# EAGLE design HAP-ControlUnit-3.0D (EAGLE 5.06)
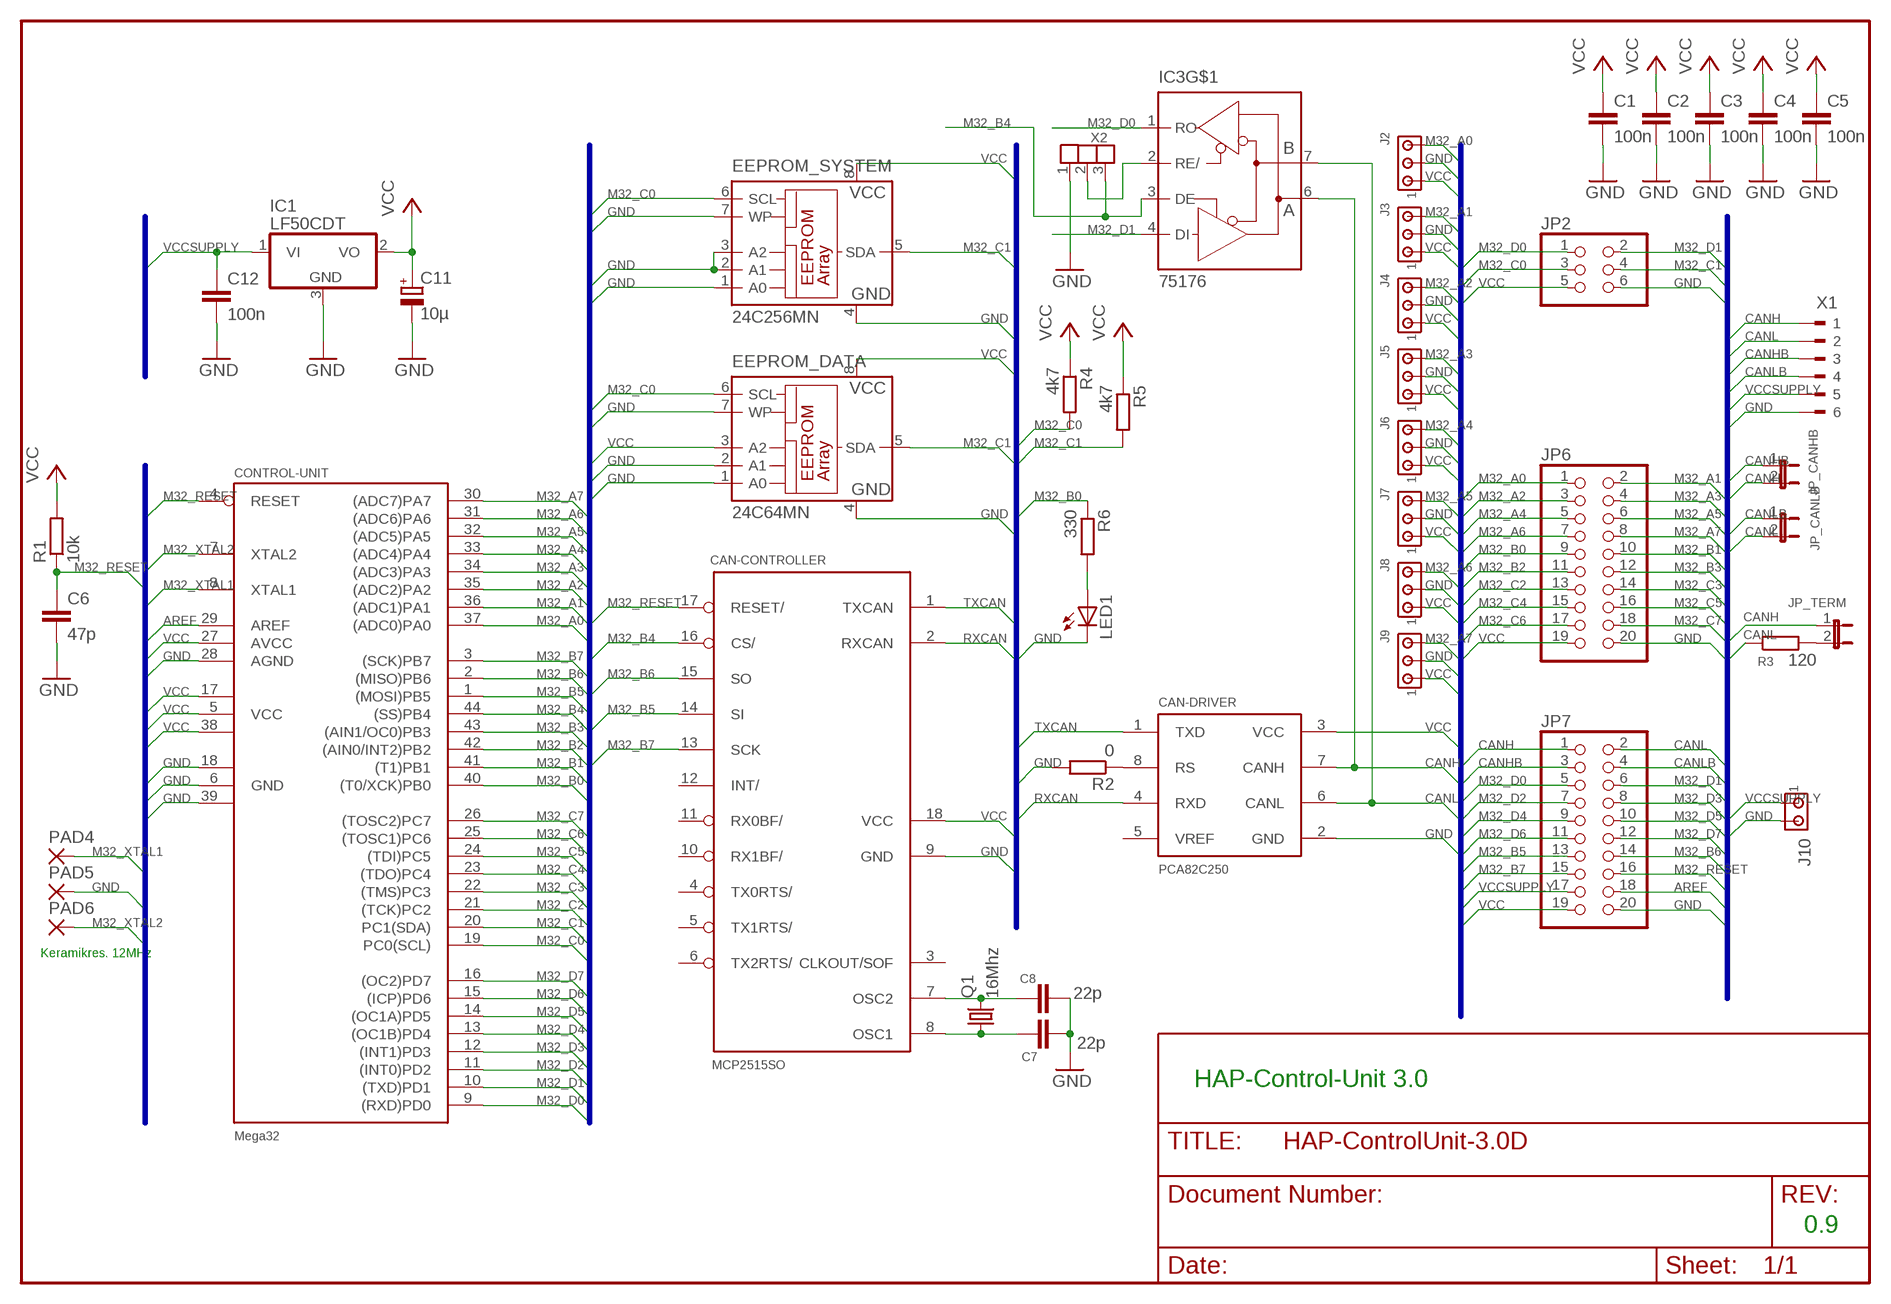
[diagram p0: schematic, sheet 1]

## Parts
C1  100n  C-EUC0805  [C0805]
C2  100n  C-EUC0805  [C0805]
C3  100n  C-EUC0805  [C0805]
C4  100n  C-EUC0805  [C0805]
C5  100n  C-EUC0805  [C0805]
C6  47p  C-EUC0805  [C0805]
C7  22p  C-EUC0805  [C0805]
C8  22p  C-EUC0805  [C0805]
C11  10µ  CPOL-EU153CLV-0405  [153CLV-0405]
C12  100n  C-EUC0805  [C0805]
CAN-CONTROLLER  MCP2515SO  [SO18L]
CAN-DRIVER  PCA82C250  PCA82C251SMD  [SO8]
CONTROL-UNIT  Mega32  MEGA32-A  [TQFP44]
EEPROM_DATA  24C64MN  24C32ASN  [SO-08]
EEPROM_SYSTEM  24C256MN  24C32ASN  [SO-08]
IC1  LF50CDT  7806DT  [TO252]
IC3  75176  [SO8]
J2  MTA03-100  [10X03MTA]
J3  MTA03-100  [10X03MTA]
J4  MTA03-100  [10X03MTA]
J5  MTA03-100  [10X03MTA]
J6  MTA03-100  [10X03MTA]
J7  MTA03-100  [10X03MTA]
J8  MTA03-100  [10X03MTA]
J9  MTA03-100  [10X03MTA]
J10  MTA02-100  [10X02MTA]
JP2  PINHD-2X3  [2X03]
JP6  PINHD-2X10  [2X10]
JP7  PINHD-2X10  [2X10]
JP_CANHB  JP1E  [JP1]
JP_CANLB  JP1E  [JP1]
JP_TERM  JP1E  [JP1]
LED1  LEDCHIP-LED0805  [CHIP-LED0805]
PAD4  1,6/0,9  [1,6/0,9]
PAD5  1,6/0,9  [1,6/0,9]
PAD6  1,6/0,9  [1,6/0,9]
Q1  16Mhz  CRYSTALHC49UP  [HC49UP]
R1  10k  R-EU_R0805  [R0805]
R2  0  R-EU_R0805  [R0805]
R3  120  R-EU_R0805  [R0805]
R4  4k7  R-EU_R0805  [R0805]
R5  4k7  R-EU_R0805  [R0805]
R6  330  R-EU_R0805  [R0805]
X1  180-6  [180-6]
X2  3-P-SMD12ZU  [3-P-SMD1]

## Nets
AREF: CONTROL-UNIT.29(AREF) JP7.18
CANH: CAN-DRIVER.7(CANH) IC3.6(A) JP7.1 JP_CANHB.2 JP_TERM.1 X1.1
CANHB: JP7.3 JP_CANHB.1 X1.3
CANL: CAN-DRIVER.6(CANL) IC3.7(B) JP7.2 JP_CANLB.2 R3.1 X1.2
CANLB: JP7.4 JP_CANLB.1 X1.4
GND [VCC_GND]: C1.2 C2.2 C3.2 C4.2 C5.2 C6.2 C7.2 C8.2 C11.- C12.2 CAN-CONTROLLER.9(GND) CAN-DRIVER.2(GND) CONTROL-UNIT.6(GND) CONTROL-UNIT.18(GND1) CONTROL-UNIT.28(AGND) CONTROL-UNIT.39(GND2) EEPROM_DATA.1(A0) EEPROM_DATA.2(A1) EEPROM_DATA.4(GND) EEPROM_DATA.7(WP) EEPROM_SYSTEM.1(A0) EEPROM_SYSTEM.2(A1) EEPROM_SYSTEM.3(A2) EEPROM_SYSTEM.4(GND) EEPROM_SYSTEM.7(WP) IC1.3(GND) J2.2 J3.2 J4.2 J5.2 J6.2 J7.2 J8.2 J9.2 J10.2 JP2.6 JP6.20 JP7.20 LED1.C PAD5.1(P) R2.2 X1.6 X2.1
M32_A0: CONTROL-UNIT.37((ADC0)PA0) J2.3 JP6.1
M32_A1: CONTROL-UNIT.36((ADC1)PA1) J3.3 JP6.2
M32_A2: CONTROL-UNIT.35((ADC2)PA2) J4.3 JP6.3
M32_A3: CONTROL-UNIT.34((ADC3)PA3) J5.3 JP6.4
M32_A4: CONTROL-UNIT.33((ADC4)PA4) J6.3 JP6.5
M32_A5: CONTROL-UNIT.32((ADC5)PA5) J7.3 JP6.6
M32_A6: CONTROL-UNIT.31((ADC6)PA6) J8.3 JP6.7
M32_A7: CONTROL-UNIT.30((ADC7)PA7) J9.3 JP6.8
M32_B0: CONTROL-UNIT.40((T0/XCK)PB0) JP6.9 R6.1
M32_B1: CONTROL-UNIT.41((T1)PB1) JP6.10
M32_B2: CONTROL-UNIT.42((AIN0/INT2)PB2) JP6.11
M32_B3: CONTROL-UNIT.43((AIN1/OC0)PB3) JP6.12
M32_B4: CAN-CONTROLLER.16(CS/) CONTROL-UNIT.44((SS)PB4) IC3.3(DE) X2.3
M32_B5: CAN-CONTROLLER.14(SI) CONTROL-UNIT.1((MOSI)PB5) JP7.13
M32_B6: CAN-CONTROLLER.15(SO) CONTROL-UNIT.2((MISO)PB6) JP7.14
M32_B7: CAN-CONTROLLER.13(SCK) CONTROL-UNIT.3((SCK)PB7) JP7.15
M32_C0: CONTROL-UNIT.19(PC0(SCL)) EEPROM_DATA.6(SCL) EEPROM_SYSTEM.6(SCL) JP2.3 R4.2
M32_C1: CONTROL-UNIT.20(PC1(SDA)) EEPROM_DATA.5(SDA) EEPROM_SYSTEM.5(SDA) JP2.4 R5.2
M32_C2: CONTROL-UNIT.21((TCK)PC2) JP6.13
M32_C3: CONTROL-UNIT.22((TMS)PC3) JP6.14
M32_C4: CONTROL-UNIT.23((TDO)PC4) JP6.15
M32_C5: CONTROL-UNIT.24((TDI)PC5) JP6.16
M32_C6: CONTROL-UNIT.25((TOSC1)PC6) JP6.17
M32_C7: CONTROL-UNIT.26((TOSC2)PC7) JP6.18
M32_D0: CONTROL-UNIT.9((RXD)PD0) IC3.1(RO) JP2.1 JP7.5
M32_D1: CONTROL-UNIT.10((TXD)PD1) IC3.4(DI) JP2.2 JP7.6
M32_D2: CONTROL-UNIT.11((INT0)PD2) JP7.7
M32_D3: CONTROL-UNIT.12((INT1)PD3) JP7.8
M32_D4: CONTROL-UNIT.13((OC1B)PD4) JP7.9
M32_D5: CONTROL-UNIT.14((OC1A)PD5) JP7.10
M32_D6: CONTROL-UNIT.15((ICP)PD6) JP7.11
M32_D7: CONTROL-UNIT.16((OC2)PD7) JP7.12
M32_RESET: C6.1 CAN-CONTROLLER.17(RESET/) CONTROL-UNIT.4(RESET) JP7.16 R1.1
M32_XTAL1: CONTROL-UNIT.8(XTAL1) PAD4.1(P)
M32_XTAL2: CONTROL-UNIT.7(XTAL2) PAD6.1(P)
N$1: LED1.A R6.2
N$2: IC3.2(RE/) X2.2
N$4: CAN-DRIVER.8(RS) R2.1
N$5: C7.1 CAN-CONTROLLER.8(OSC1) Q1.1
N$6: JP_TERM.2 R3.2
N$7: C8.1 CAN-CONTROLLER.7(OSC2) Q1.2
RXCAN: CAN-CONTROLLER.2(RXCAN) CAN-DRIVER.4(RXD)
TXCAN: CAN-CONTROLLER.1(TXCAN) CAN-DRIVER.1(TXD)
VCC [VCC_GND]: C1.1 C2.1 C3.1 C4.1 C5.1 C11.+ CAN-CONTROLLER.18(VCC) CAN-DRIVER.3(VCC) CONTROL-UNIT.5(VCC) CONTROL-UNIT.17(VCC1) CONTROL-UNIT.27(AVCC) CONTROL-UNIT.38(VCC2) EEPROM_DATA.3(A2) EEPROM_DATA.8(VCC) EEPROM_SYSTEM.8(VCC) IC1.2(VO) J2.1 J3.1 J4.1 J5.1 J6.1 J7.1 J8.1 J9.1 JP2.5 JP6.19 JP7.19 R1.2 R4.1 R5.1
VCCSUPPLY [VCC_GND]: C12.1 IC1.1(VI) J10.1 JP7.17 X1.5
Unconnected: CAN-CONTROLLER.3(CLKOUT/SOF) CAN-CONTROLLER.4(TX0RTS/) CAN-CONTROLLER.5(TX1RTS/) CAN-CONTROLLER.6(TX2RTS/) CAN-CONTROLLER.10(RX1BF/) CAN-CONTROLLER.11(RX0BF/) CAN-CONTROLLER.12(INT/) CAN-DRIVER.5(VREF)

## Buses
M32_RESET,M32_XTAL2,M32_XTAL1,M32_AREF,M32_AVCC,M32_AGND,M32_A[0..7],M32_B[0..7],M32_C[0..7],M32_D[0..7],VCC,GND,TXCAN,RXCAN,CANH,CANHB,CANL,CANLB,VCCSUPPLY,M32_XTAL1,M32_XTAL2,MCP_OSC1,MCP_OSC2,AREF

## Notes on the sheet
- Keramikres. 12MHz
- HAP-Control-Unit 3.0
- 0.9

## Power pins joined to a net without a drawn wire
GND: IC3.5(GND)
VCC: IC3.8(VCC)

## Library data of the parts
C1-C8 C12 = rcl:C-EU: CAPACITOR, European symbol
C11 = rcl:CPOL-EU: POLARIZED CAPACITOR, European symbol
CAN-CONTROLLER = MCP2515_MT:MCP2515*: MCP2515 Standalone CAN-Controller by Microchip Eagle-Lib. by MartinThomas
CAN-DRIVER = 82C250SMD:PCA82C251SMD
CONTROL-UNIT = atmel:MEGA32: MICROCONTROLLER 32 Kbytes FLASH 2 Kbytes SRAM 1 Kbytes EEPROM USART 8-channel 10 bit ADC Source: www.atmel.com .. doc2503.pdf
EEPROM_DATA EEPROM_SYSTEM = microchip:24*: Serial EEPROM I2C
IC1 = linear:78*: Positive VOLTAGE REGULATOR Source: http://cache.national.com/ds/LM/LM78L05.pdf http://www.fairchildsemi.com/ds/LM/LM7805.pdf
IC3 = OWN:75176
J2-J9 = con-amp:MTA03-100: AMP connector
J10 = con-amp:MTA02-100: AMP connector
JP2 = pinhead:PINHD-2X3: PIN HEADER
JP6 JP7 = pinhead:PINHD-2X10: PIN HEADER
JP_CANHB JP_CANLB JP_TERM = jumper:JP1E: JUMPER
LED1 = led:LED: LED
PAD4-PAD6 = wirepad:1,6/0,9: THROUGH-HOLE PAD
Q1 = crystal:CRYSTAL: CRYSTAL
R1-R6 = rcl:R-EU_: RESISTOR, European symbol
X1 = con-weidmueller-sl35:180-6: WEIDMUELLER CLAMP CONNECTOR
X2 = OWN:3-P-SMD

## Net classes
0 default: width 0.15 mm, drill 0.3 mm, clearance 0.15 mm
1 VCC_GND: width 0.25 mm, drill 0.3 mm, clearance 0.15 mm

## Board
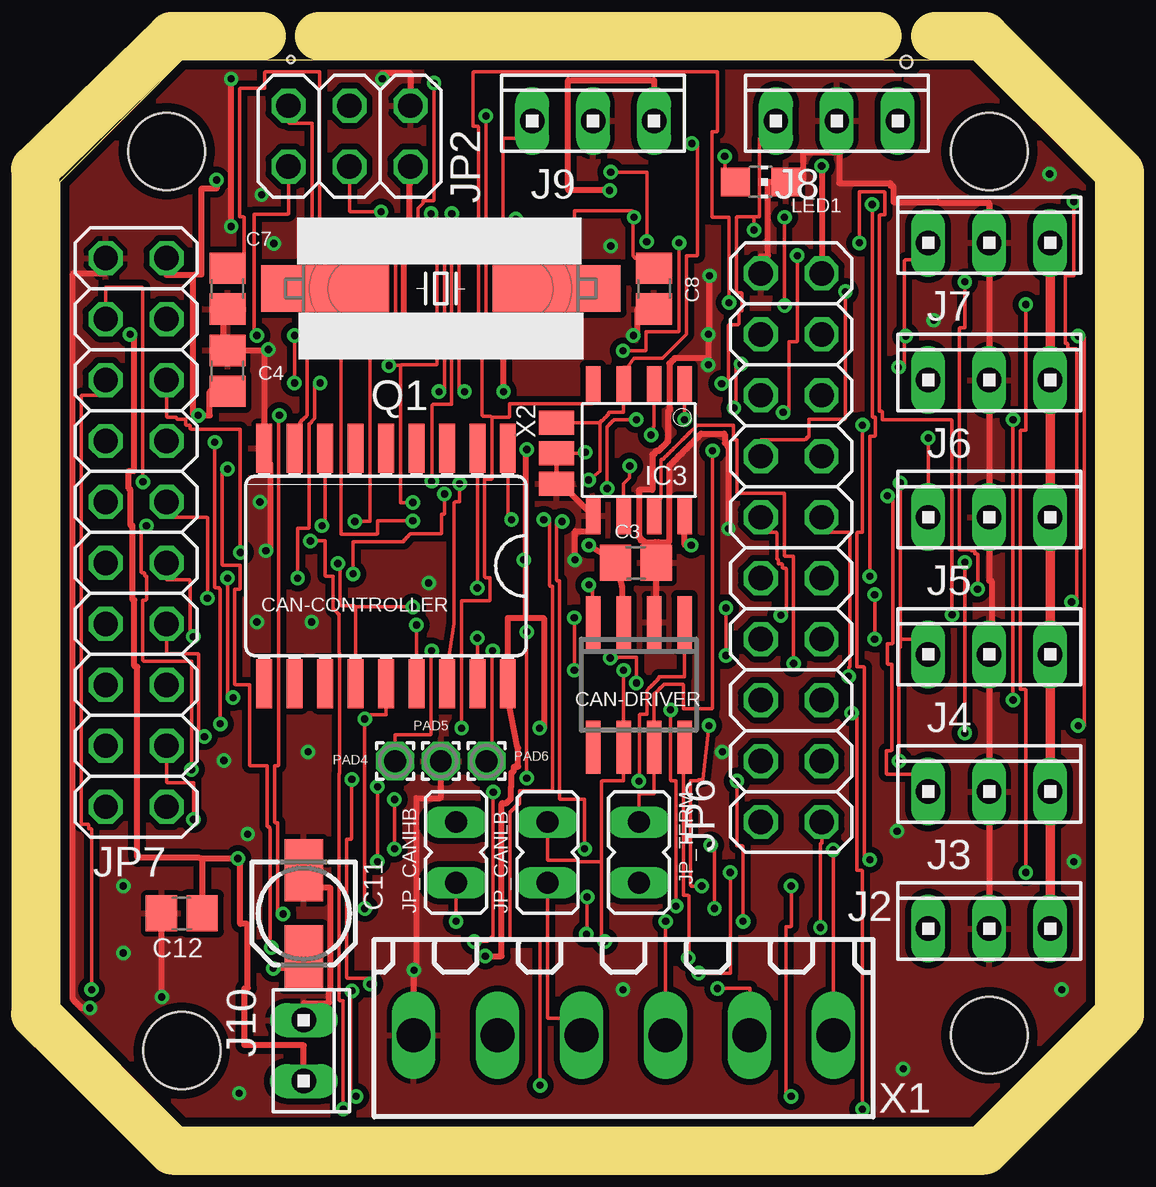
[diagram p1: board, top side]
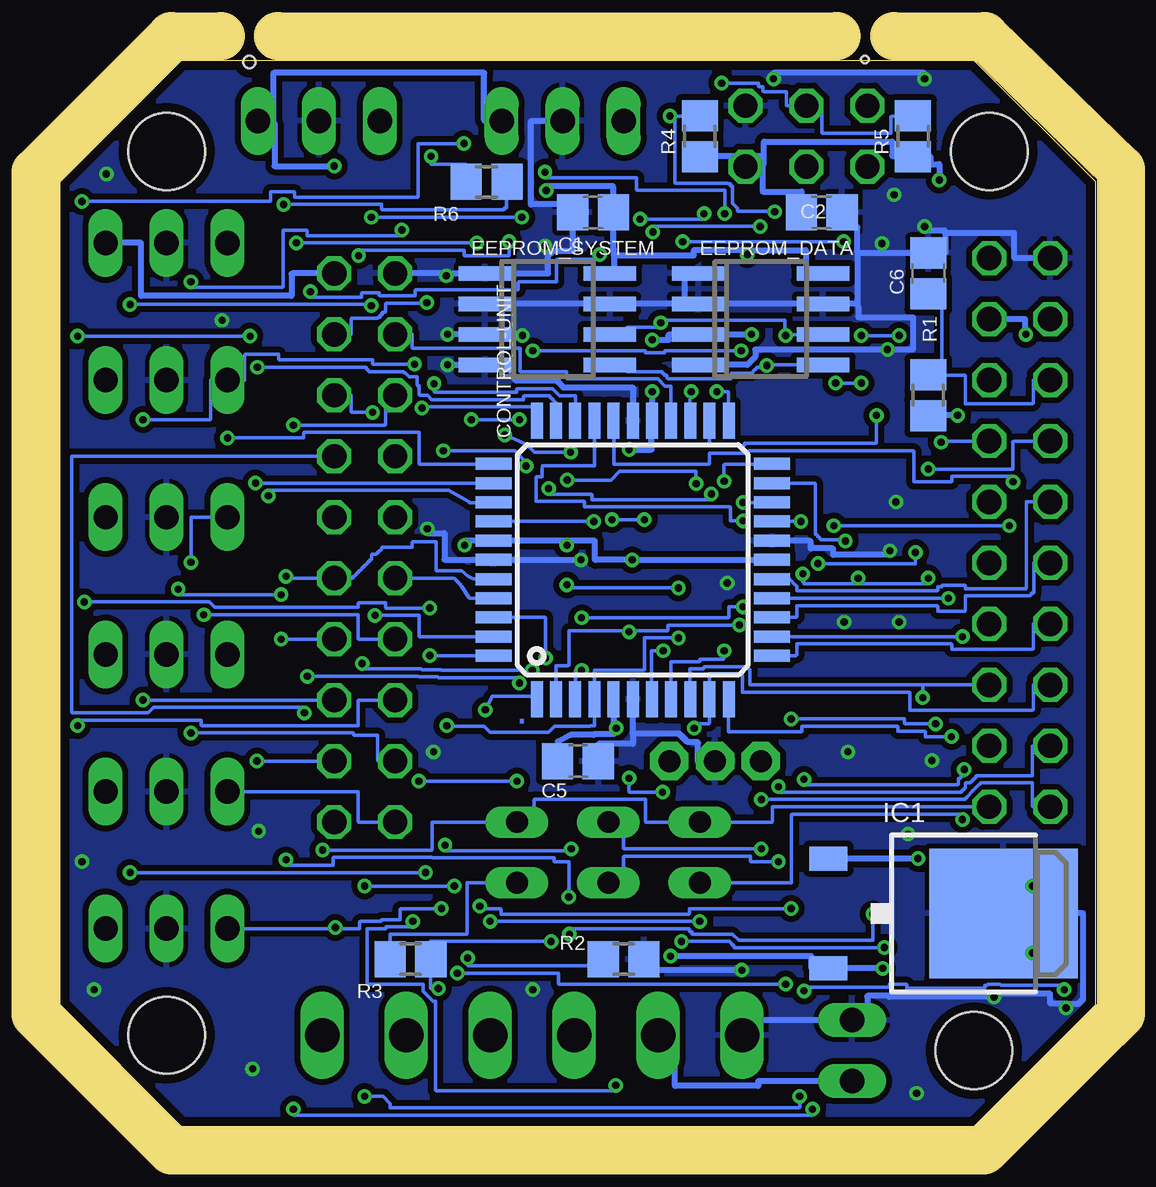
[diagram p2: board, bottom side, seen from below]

Size 43.18 x 44.45 mm. Coordinates in mm from the lower left corner, seen from the top.
Outline: 5.08,0 38.1,0 43.18,5.08 43.18,39.37 38.1,44.45 5.08,44.45 0,39.37 0,5.08 5.08,0
Copper layers (1*16): Top 0.035mm / dielectric 1.5mm / Bottom 0.035mm
Design rules "leiton *": minimum track width 0.15mm, minimum drill 0.3mm, track to track 6mil, track to pad 6mil, pad to pad 6mil, via to via 6mil, smd to smd 0mil, copper to edge 0.4mm, drill to drill 0.18mm, minimum pad ring 0.2mm, minimum via ring 0.15mm, stop-mask expansion 3mil, vias tented up to drill 0mil, thermal gap 8mil
Holes 3.2 mm at 4.45,40.64 38.73,3.81 5.08,3.18 38.73,40.64
Holes 0.5 mm at 35.28,44.37
Holes 0.3 mm at 9.63,44.48
Milling: 12 lines

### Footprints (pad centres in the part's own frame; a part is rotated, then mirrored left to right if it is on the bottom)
C0805 = smd 1.3 x 1.5: 1 -0.85,0; 2 0.85,0
153CLV-0405 = smd 2.6 x 1.6: + 1.8,0; - -1.8,0
SO18L = smd 0.66 x 2.032: 1 -5.08,-4.902; 2 -3.81,-4.902; 3 -2.54,-4.902; 4 -1.27,-4.902; 5 0,-4.902; 6 1.27,-4.902; 7 2.54,-4.902; 8 3.81,-4.902; 9 5.08,-4.902; 10 5.08,4.902; 11 3.81,4.902; 12 2.54,4.902; 13 1.27,4.902; 14 0,4.902; 15 -1.27,4.902; 16 -2.54,4.902; 17 -3.81,4.902; 18 -5.08,4.902
SO8 = smd 0.6 x 2.2: 1 -1.905,-2.6; 2 -0.635,-2.6; 3 0.635,-2.6; 4 1.905,-2.6; 5 1.905,2.6; 6 0.635,2.6; 7 -0.635,2.6; 8 -1.905,2.6
TQFP44 = smd 1.5 x 0.5: 1 -5.8,4; 2 -5.8,3.2; 3 -5.8,2.4; 4 -5.8,1.6; 5 -5.8,0.8; 6 -5.8,0; 7 -5.8,-0.8; 8 -5.8,-1.6; 9 -5.8,-2.4; 10 -5.8,-3.2; 11 -5.8,-4; 23 5.8,-4; 24 5.8,-3.2; 25 5.8,-2.4; 26 5.8,-1.6; 27 5.8,-0.8; 28 5.8,0; 29 5.8,0.8; 30 5.8,1.6; 31 5.8,2.4; 32 5.8,3.2; 33 5.8,4 | smd 0.5 x 1.5: 12 -4,-5.8; 13 -3.2,-5.8; 14 -2.4,-5.8; 15 -1.6,-5.8; 16 -0.8,-5.8; 17 0,-5.8; 18 0.8,-5.8; 19 1.6,-5.8; 20 2.4,-5.8; 21 3.2,-5.8; 22 4,-5.8; 34 4,5.8; 35 3.2,5.8; 36 2.4,5.8; 37 1.6,5.8; 38 0.8,5.8; 39 0,5.8; 40 -0.8,5.8; 41 -1.6,5.8; 42 -2.4,5.8; 43 -3.2,5.8; 44 -4,5.8
SO-08 = smd 0.6 x 2.2: 1 -1.905,-2.6; 2 -0.635,-2.6; 3 0.635,-2.6; 4 1.905,-2.6; 5 1.905,2.6; 6 0.635,2.6; 7 -0.635,2.6; 8 -1.905,2.6
TO252 = smd 1 x 1.6: 1 -2.28,-4.8; 2 2.28,-4.8 | smd 5.4 x 6.2: 3 0,2.5
SO8' = smd 0.61 x 1.524: 1 -1.905,-2.743; 2 -0.635,-2.743; 3 0.635,-2.743; 4 1.905,-2.743; 5 1.905,2.743; 6 0.635,2.743; 7 -0.635,2.743; 8 -1.905,2.743
10X03MTA = drill 1.016 long: 1 2.54,0; 2 0,0; 3 -2.54,0
10X02MTA = drill 1.016 long: 1 1.27,0; 2 -1.27,0
2X03 = drill 1.016 octagon: 1 -2.54,-1.27; 2 -2.54,1.27; 3 0,-1.27; 4 0,1.27; 5 2.54,-1.27; 6 2.54,1.27
2X10 = drill 1.016 octagon: 1 -11.43,-1.27; 2 -11.43,1.27; 3 -8.89,-1.27; 4 -8.89,1.27; 5 -6.35,-1.27; 6 -6.35,1.27; 7 -3.81,-1.27; 8 -3.81,1.27; 9 -1.27,-1.27; 10 -1.27,1.27; 11 1.27,-1.27; 12 1.27,1.27; 13 3.81,-1.27; 14 3.81,1.27; 15 6.35,-1.27; 16 6.35,1.27; 17 8.89,-1.27; 18 8.89,1.27; 19 11.43,-1.27; 20 11.43,1.27
JP1 = drill 0.914 long: 1 0,-1.27; 2 0,1.27
CHIP-LED0805 = smd 1.2 x 1.2: A 0,-1.05; C 0,1.05
1,6/0,9 = drill 0.914 pad 1.6 octagon: 1 0,0
HC49UP = smd 5.334 x 1.93: 1 -4.826,0; 2 4.826,0
R0805 = smd 1.3 x 1.5: 1 -0.85,0; 2 0.85,0
180-6 = drill 1.422 long: 1 -8.75,0; 2 -5.25,0; 3 -1.75,0; 4 1.75,0; 5 5.25,0; 6 8.75,0
3-P-SMD1 = smd 0.991 x 1.448: 1 0,0; 2 1.27,0; 3 2.54,0

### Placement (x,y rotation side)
C1  20.96,38.1 180 bottom
C2  11.43,38.1 0 bottom
C3  24,23.5 0 top
C4  6.99,31.5 90 top
C5  21.59,15.24 0 bottom
C6  6.99,35.56 90 bottom
C7  6.99,34.93 270 top
C8  24.77,34.93 270 top
C11  10.16,8.89 270 top
C12  5.08,8.89 180 top
CAN-CONTROLLER  13.59,23.37 180 top
CAN-DRIVER  24.13,18.41 180 top
CONTROL-UNIT  19.3,23.62 90 bottom
EEPROM_DATA  13.97,33.66 270 bottom
EEPROM_SYSTEM  22.86,33.66 270 bottom
IC1  6.35,8.89 270 bottom
IC3  75176  [SO8']  24.13,28.19 180 top
J2  38.73,8.26 0 top
J3  38.73,13.97 0 top
J4  38.73,19.69 0 top
J5  38.73,25.4 0 top
J6  38.73,31.12 0 top
J7  38.73,36.83 0 top
J8  32.39,41.91 0 top
J9  22.23,41.91 0 top
J10  10.16,3.18 270 top
JP2  12.06,41.28 0 top
JP6  30.48,24.13 90 top
JP7  3.18,24.77 90 top
JP_CANHB  16.51,11.43 0 top
JP_CANLB  20.32,11.43 0 top
JP_TERM  24.13,11.43 180 top
LED1  29.21,39.37 270 top
PAD4  13.97,15.24 0 top
PAD5  15.88,15.24 180 top
PAD6  17.78,15.24 180 top
Q1  15.88,34.93 0 top
R1  6.99,30.48 270 bottom
R2  19.69,6.99 0 bottom
R3  28.58,6.99 180 bottom
R4  16.51,41.28 90 bottom
R5  7.62,41.28 90 bottom
R6  25.4,39.37 180 bottom
X1  23.5,3.81 180 top
X2  20.7,26.8 90 top

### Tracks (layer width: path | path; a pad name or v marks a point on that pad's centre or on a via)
AREF  (via drill 0.3)
  Top 0.15: v3.45,26.87 3.45,34.95 3.43,34.98 1.91,34.98 JP7.18
  Bottom 0.15: v3.45,26.87 3.45,27.08 3.48,27.1 5.99,27.1 5.99,26.9 6.02,26.87 7.6,26.87 7.6,28.14 7.62,28.17 14.45,28.17 14.48,28.14 14.48,28.09 14.5,28.07 16.1,28.07 16.1,27.64 16.13,27.61 20.09,27.61 20.09,29.41 CONTROL-UNIT.29
CANH  (via drill 0.3)
  Top 0.15: v23.75,27.53 23.75,27.05 23.5,26.8 IC3.6 | v27.2,28.17 27.2,17.45 27.18,17.42 25.98,17.42 25.98,18.41 25.96,18.44 25.17,18.44 25.15,18.41 25.15,18.39 25.12,18.36 25.09,18.36 25.07,18.34 25.07,18.31 25.04,18.29 25.02,18.29 24.99,18.26 24.99,18.24 24.97,18.21 24.94,18.21 24.92,18.19 24.92,18.16 24.89,18.14 24.87,18.14 24.84,18.11 24.84,18.09 24.82,18.06 24.79,18.06 24.77,18.03 CAN-DRIVER.7 24.77,13.87 24.16,13.87 24.13,13.84 JP_TERM.1 | v32.23,11.53 32.23,3.81 X1.1
  Bottom 0.15: JP7.1 13.49,13.33 13.49,12.72 13.51,12.7 JP_CANHB.2 18.74,12.7 18.77,12.72 18.77,13.64 23.39,13.64 23.42,13.61 23.42,12.7 JP_TERM.1 27.66,12.7 27.66,11.56 27.69,11.53 v32.23,11.53 | v27.2,28.17 24.22,28.17 23.75,27.7 v23.75,27.53
CANHB  (via drill 0.3)
  Top 0.15: JP_CANHB.1 v16.51,8.56 | v25.25,8.56 X1.3 | JP7.3 4.45,14.35 4.47,14.33 5.56,14.33 v5.56,12.8
  Bottom 0.15: v16.51,8.56 v25.25,8.56 | v5.56,12.8 5.56,13.03 12.67,13.03 12.7,13.01 12.7,10.16 JP_CANHB.1
CANL  (via drill 0.3)
  Top 0.15: v27.41,5.77 28.75,5.77 X1.2 | IC3.7 24.77,26.16 24.79,26.19 25.04,26.19 25.04,27.79 25.07,27.81 25.15,27.81 25.17,27.84 25.17,27.86 25.2,27.89 25.22,27.89 25.25,27.91 25.25,27.94 25.27,27.97 25.3,27.97 25.32,27.99 25.32,28.02 25.35,28.04 25.38,28.04 25.4,28.07 25.4,28.09 25.43,28.12 25.45,28.12 25.48,28.14 25.48,28.17 25.5,28.19 25.53,28.19 25.55,28.22 25.55,28.25 25.58,28.27 25.6,28.27 25.93,28.6 25.93,28.63 25.96,28.65 25.98,28.65 26.01,28.68 26.01,28.7 26.04,28.73 26.06,28.73 26.09,28.75 26.09,28.78 26.11,28.8 26.14,28.8 26.16,28.83 26.16,28.85 26.19,28.88 26.21,28.88 26.24,28.91 26.24,28.93 26.26,28.93 26.57,29.23 28.07,29.23 28.07,28.65 28.09,28.63 28.22,28.63 28.22,26.42 28.25,26.39 30.2,26.39 30.2,23.8 30.23,23.77 30.58,23.77 v30.58,19.3 | v23.5,19.02 CAN-DRIVER.6 23.5,14.43 22.61,14.43 22.58,14.4 22.58,11.05 | JP_CANLB.2 20.32,11.13 20.34,11.1 21.59,11.1 21.59,11.07 21.62,11.05 22.58,11.05 | v13.95,13.64 v13.95,11.58 | v22.71,7.72 22.58,7.72 22.58,11.05
  Bottom 0.15: v27.41,5.77 27.74,5.77 27.74,6.99 R3.1 27.74,7.04 27.74,7.72 v22.71,7.72 | v30.58,19.3 30.58,19.08 28.12,19.08 28.09,19.05 27.3,19.05 27.28,19.02 v23.5,19.02 | JP7.2 2.62,13.33 2.64,13.36 2.64,14.33 4.8,14.33 4.83,14.3 4.83,14.28 4.85,14.28 5.11,14.02 5.13,14.02 5.13,13.99 5.38,13.74 5.38,13.72 5.41,13.72 5.44,13.69 5.44,13.64 v13.95,13.64 | v13.95,11.58 19.66,11.58 19.69,11.61 19.69,12.7 JP_CANLB.2
CANLB  (via drill 0.3)
  Top 0.15: JP_CANLB.1 20.32,4.55 20.34,4.52 21.74,4.52 X1.4 | v13.23,14.17 v13.23,11.05
  Bottom 0.15: JP7.4 2.62,15.88 2.64,15.85 2.64,14.63 4.98,14.63 5,14.61 5,14.55 5.03,14.53 5.06,14.53 5.08,14.5 5.08,14.48 5.11,14.45 5.13,14.45 5.16,14.43 5.16,14.4 5.18,14.38 5.21,14.38 5.23,14.35 5.23,14.33 5.41,14.33 5.44,14.3 5.44,14.12 5.46,14.1 5.49,14.1 5.51,14.07 5.51,14.05 5.54,14.02 5.56,14.02 5.59,13.99 5.59,13.97 5.61,13.95 13.21,13.95 13.23,13.97 v13.23,14.17 | v13.23,11.05 14.38,11.05 14.4,11.07 14.4,11.28 19.66,11.28 19.69,11.25 19.69,10.16 JP_CANLB.1
GND  (via drill 0.3)
  Top 0.25: v4.24,5.41 4.24,8.89 C12.2 | J10.2 10.16,5.16 11.2,5.16 11.23,5.18 11.23,5.66 11.28,5.72 11.28,9.96 10.19,9.96 10.16,9.98 C11.- | X1.6 14.76,3.81 v14.76,6.53 14.86,6.58 14.86,13.69 15.85,13.69 15.88,13.72 PAD5.1 | J2.2 J3.2 J4.2 38.73,20.4 38.81,20.4 38.84,20.42 38.84,22.73 38.76,22.73 38.73,22.76 J5.2 J6.2 J7.2 38.73,38.48 38.71,38.51 36.63,38.51 36.6,38.53 34.75,38.53 34.75,39.17 34.72,39.19 34.65,39.19 34.62,39.22 34.62,39.29 34.59,39.32 32.49,39.32 32.49,40.59 J8.2 32.39,40.64 32.36,40.62 30.99,40.62 30.99,39.4 30.96,39.37 LED1.C 29.52,39.37 29.52,36.3 29.49,36.27 29.21,36.27 JP6.20 | C7.2 6.99,34.09 6.83,34.09 6.83,32.33 C4.2 7.09,32.33 8.51,32.33 | v8.58,24 8.76,24 8.76,27.61 8.74,27.64 8.51,27.64 CAN-CONTROLLER.9 8.51,32.33 | v8.69,32.39 8.61,32.39 8.51,32.33 | v21.46,23.62 21.46,24.79 21.49,24.82 22.23,24.82 IC3.5 20.88,26.8 X2.1 | CAN-DRIVER.2 24.77,21.72 24.82,21.72 24.84,21.74 24.84,23.5 C3.2 24.84,23.6 24.84,24.33 | 24.84,24.33 24.82,24.36 24.33,24.36 24.33,24.41 24.31,24.44 24.21,24.44 24.21,24.54 24.18,24.56 24.16,24.56 24.13,24.59 24.13,26.52 24.16,26.54 24.69,26.54 24.69,28.02 24.71,28.04 24.79,28.04 24.82,28.07 24.82,28.14 24.84,28.17 24.97,28.17 24.99,28.19 24.99,28.22 25.02,28.25 25.04,28.25 25.07,28.27 25.07,28.3 25.09,28.32 25.12,28.32 25.15,28.35 25.15,28.37 25.17,28.4 25.2,28.4 25.22,28.42 25.22,28.45 25.25,28.47 25.27,28.47 25.3,28.5 25.3,28.52 25.32,28.55 25.35,28.55 25.35,29.82 25.38,29.84 25.4,29.84 25.4,31.8 25.43,31.83 25.45,31.83 25.48,31.85 25.48,31.88 25.5,31.9 25.53,31.9 25.53,31.93 25.55,31.95 25.58,31.95 25.58,31.98 25.63,32.03 27.03,32.03
  Top 0.25: 27.03,32.03 v27.03,31.75 | v27.86,24.92 27.86,28.35 27.84,28.37 27.81,28.37 27.81,28.4 27.71,28.5 27.71,28.85 27.69,28.88 26.72,28.88 26.7,28.85 26.7,28.83 26.67,28.8 26.65,28.8 26.62,28.78 26.62,28.75 26.59,28.73 26.57,28.73 26.54,28.7 26.54,28.68 26.52,28.65 26.49,28.65 26.47,28.63 26.47,28.6 26.44,28.58 26.42,28.58 26.39,28.55 26.39,28.52 26.37,28.5 26.34,28.5 26.31,28.47 26.31,28.45 26.29,28.42 26.26,28.42 26.24,28.4 26.24,28.37 26.21,28.35 26.19,28.35 26.16,28.32 26.16,28.3 26.14,28.27 26.11,28.27 26.09,28.25 26.09,28.22 26.06,28.19 26.04,28.19 26.01,28.17 26.01,28.14 25.98,28.12 25.96,28.12 25.93,28.09 25.93,28.07 25.91,28.04 25.88,28.04 25.86,28.02 25.86,27.99 25.83,27.97 25.81,27.97 25.78,27.94 25.78,27.91 25.76,27.89 25.73,27.89 25.71,27.86 25.71,27.84 25.68,27.81 25.65,27.81 25.63,27.79 25.63,27.76 25.6,27.74 25.58,27.74 25.55,27.71 25.55,27.69 25.53,27.66 25.5,27.66 25.48,27.64 25.48,27.61 25.45,27.58 25.43,27.58 25.4,27.56 25.4,24.38 25.38,24.36 24.94,24.36 24.84,24.33 | v23.9,32.97 24.05,32.97 24.08,33 24.08,34.09 24.77,34.09 C8.2 | JP2.6 14.61,43.89 14.58,43.92 13.44,43.92 v13.44,43.66 | v7.14,37.52 v7.14,43.66 | 27.03,32.03 v27.03,33.02 27.08,33.12 v27.08,35.46 | v1.25,4.95 0.89,4.95 0.86,4.98 0.86,5 0.84,5.03 0.81,5.03 0.79,5.06 0.79,5.08 0.76,5.11 0.74,5.11 0.71,5.13 0.71,5.16 0.69,5.18 0.66,5.18 0.63,5.21 0.63,5.23 0.61,5.26 0.58,5.26 0.56,5.28 0.56,5.31 0.53,5.33 0.53,35.54 0.56,35.56 1.91,35.56 JP7.20
  Bottom 0.25: 1.25,5.13 1.88,5.13 1.91,5.16 1.91,5.54 4.17,5.54 4.19,5.51 v4.24,5.41 8.61,5.41 8.64,5.44 8.64,5.46 9.5,5.46 9.53,5.44 9.53,4.45 J10.2 14.02,4.45 14.05,4.42 14.05,3.81 X1.6 | 1.25,5.13 0.71,5.13 0.69,5.16 0.69,5.18 0.66,5.21 0.63,5.21 0.61,5.23 0.61,5.26 0.58,5.28 0.56,5.28 0.53,5.31 0.53,8.87 0.56,8.89 IC1.3 | 19.3,16.38 19.3,15.95 20.73,15.95 20.75,15.93 20.75,15.24 C5.2 | 19.3,16.38 CONTROL-UNIT.6 | PAD5.1 16.59,15.24 16.59,16 16.61,16.03 17.02,16.03 17.02,16.05 17.04,16.08 17.09,16.08 17.09,16.13 17.12,16.15 17.17,16.15 17.17,16.2 17.2,16.23 17.25,16.23 17.25,16.28 17.27,16.31 17.32,16.31 17.35,16.33 17.35,16.36 17.37,16.38 19.3,16.38 | v14.76,6.53 18.85,6.53 18.85,6.99 R2.2 | J9.2 23.52,41.91 23.55,41.89 23.55,38.43 21.79,38.43 21.79,38.2 C1.2 21.79,38.1 21.79,36.5 22.68,36.5 22.71,36.47 22.71,36.4 22.73,36.37 22.81,36.37 22.84,36.35 22.84,35.56 EEPROM_SYSTEM.1 27.08,35.56 | 27.08,35.56 JP6.20 | v8.58,24 8.58,23.85 8.61,23.83 10.95,23.83 10.95,24.08 10.97,24.11 11.89,24.11 11.89,24.38 11.91,24.41 13.49,24.41 CONTROL-UNIT.18 | EEPROM_DATA.4 14.53,31.75 14.2,32.08 14.2,32.39 v8.69,32.39 7.65,32.39 7.62,32.41 7.62,33.73 9.88,33.73 9.91,33.76 9.91,34.19 9.96,34.29 | v21.46,23.62 CONTROL-UNIT.39 27.13,23.62 27.15,23.65 27.15,24.74 27.84,24.74 27.86,24.77 v27.86,24.92 | CONTROL-UNIT.28 19.3,30.81 22.2,30.81 22.43,31.04 22.43,31.12 24.21,31.12 24.23,31.14 24.23,31.22 24.26,31.24 24.33,31.24 24.36,31.27 24.36,31.75 EEPROM_SYSTEM.4 v27.03,31.75 | v23.9,32.97 23.93,33 24.74,33 24.77,33.02 EEPROM_SYSTEM.3 | EEPROM_DATA.2 EEPROM_DATA.7 9.96,34.29
  Bottom 0.25: EEPROM_DATA.2 EEPROM_SYSTEM.7 EEPROM_SYSTEM.2 24.77,34.19 24.77,33.12 EEPROM_SYSTEM.3 | EEPROM_DATA.1 17.09,35.56 17.12,35.54 17.12,34.39 EEPROM_DATA.2 | 9.91,36.4 6.99,36.4 C6.2 6.88,36.4 6.27,36.4 6.27,37.21 6.25,37.24 | 9.91,36.4 9.93,36.42 9.93,37.47 10.57,37.47 10.59,37.49 10.59,38.1 C2.2 | JP7.20 3.38,36.2 3.4,36.22 3.4,37.24 6.25,37.24 | v13.44,43.66 13.44,43.92 7.16,43.92 7.14,43.89 v7.14,43.66 | v7.14,37.52 7.14,37.34 6.3,37.34 6.25,37.24 | 9.96,34.29 9.93,34.32 9.93,36.3 9.91,36.4 | EEPROM_SYSTEM.3 v27.03,33.02 | v27.08,35.46 27.08,35.56 | v1.25,4.95 1.25,5.13
  other vias: 10.34,15.62 27.61,15.62 7.82,12.19 23.47,5.72 8.33,26.04 15.37,22.66 36.42,33.6 41.25,39.7 7.47,1.4 2.64,7.24 2.64,10.03 6.83,15.27 8.2,21.03 10.49,21.03 8.92,36.8 8.41,38.84 35.15,2.41 34.9,12.32 42.27,11.05 41.76,5.72 22.96,36.7
  pour Top (isolate 0.25): 0,39.37 5.08,44.45 38.1,44.45 43.18,39.37 43.18,5.08 38.1,0 5.08,0 0,5.08
  pour Bottom (isolate 0.25): 0,39.37 5.08,44.45 38.1,44.45 43.18,39.37 43.18,5.08 38.1,0 5.08,0 0,5.08
M32_A0  (via drill 0.3)
  Top 0.15: v20.93,25.22 20.7,25.22 20.7,22.78 20.73,22.76 20.83,22.76 20.83,13.67 20.85,13.64 21.87,13.64 v21.87,11.58 | v27.13,11.74 27.28,11.74 v27.28,9.09 | JP6.1 31.75,11.81 31.73,11.79 31.7,11.79 v31.7,8.31
  Bottom 0.15: v20.93,25.22 CONTROL-UNIT.37 | v21.87,11.58 21.87,11.51 27.1,11.51 27.13,11.53 v27.13,11.74 | v27.28,9.09 28.98,9.09 29.01,9.07 29.01,8.64 29.77,8.64 29.79,8.61 29.79,8.56 30.66,8.56 30.68,8.53 30.68,8.26 31.7,8.26 | 31.7,8.26 J2.3 | 31.7,8.26 v31.7,8.31
M32_A1  (via drill 0.3)
  Top 0.15: v34.49,26.29 34.72,26.29 34.72,20.14 34.7,20.12 34.49,20.12 34.49,19.3 34.52,19.28 34.67,19.28 34.67,15.7 34.65,15.67 34.44,15.67 34.44,14.71 34.47,14.68 36.2,14.68 J3.3
  Bottom 0.15: v34.49,26.29 34.49,26.49 34.47,26.52 26.98,26.52 26.14,26.04 26.11,26.01 25.12,26.01 CONTROL-UNIT.36 | JP6.2 30.73,12.7 30.76,12.72 30.76,13.97 J3.3
M32_A2  (via drill 0.3)
  Top 0.15: v35.03,26.82 35.03,20.34 35.05,20.32 | 35.05,20.32 36.2,20.32 J4.3 | v34.98,15.24 34.98,19.96 35,19.99 35.03,19.99 35.03,20.27 35.05,20.32
  Bottom 0.15: v35.03,26.82 25.12,26.82 CONTROL-UNIT.35 | JP6.3 v34.98,15.24
M32_A3  (via drill 0.3)
  Top 0.15: J5.3 v36.2,28.7 | v37.72,16.41 v37.72,23.52
  Bottom 0.15: v36.2,28.7 33.02,28.7 33.02,28.91 33,28.93 28.22,28.93 28.22,27.64 28.19,27.61 25.12,27.61 CONTROL-UNIT.34 | JP6.4 29.92,15.24 29.95,15.26 29.95,16.31 30.91,16.31 30.94,16.33 30.94,16.38 30.96,16.41 v37.72,16.41 | v37.72,23.52 37.72,25.4 J5.3
M32_A4  (via drill 0.3)
  Top 0.15: v28.09,29.95 28.17,29.95 28.17,31.75 28.19,31.78 v28.4,31.78 | v39.73,17.78 v39.73,29.46
  Bottom 0.15: v28.09,29.95 28.09,29.97 28.07,30 23.29,30 23.29,29.44 CONTROL-UNIT.33 | v28.4,31.78 30.12,31.78 30.15,31.8 30.15,31.95 34.04,31.95 34.06,31.98 34.06,32.18 35.46,32.18 35.48,32.16 35.48,31.12 J6.3 36.91,31.12 36.91,29.49 36.93,29.46 v39.73,29.46 | JP6.5 v39.73,17.78
M32_A5  (via drill 0.3)
  Top 0.15: v34.95,31.65 35.2,31.65 35.2,32.94 | 35.2,32.94 35.2,36.09 35.23,36.12 36.2,36.12 J7.3 | v42.44,16.71 42.7,16.71 42.7,32.92 42.67,32.94 v42.44,32.94 | v35.26,32.94 35.2,32.94
  Bottom 0.15: v34.95,31.65 30.43,31.65 30.43,31.6 30.4,31.57 30.35,31.57 30.33,31.55 30.33,31.5 30.3,31.47 28.85,31.47 28.85,31.45 28.83,31.42 28.8,31.42 28.63,31.24 28.3,31.24 28.3,30.91 28.27,30.89 28.22,30.89 28.22,30.51 28.19,30.48 27.86,30.48 27.69,30.3 23.85,30.3 23.85,30.43 23.83,30.46 22.78,30.46 22.76,30.43 22.76,30.4 22.73,30.4 22.71,30.38 22.71,30.35 22.68,30.33 22.66,30.33 22.63,30.3 22.63,30.28 22.61,30.25 22.58,30.25 22.55,30.23 22.55,30.2 22.53,30.18 22.5,30.18 22.5,29.44 CONTROL-UNIT.32 | JP6.6 30.73,17.78 30.76,17.76 30.76,16.71 37.26,16.71 37.29,16.74 37.29,16.94 42.42,16.94 42.44,16.92 v42.44,16.71 | v42.44,32.94 v35.26,32.94
M32_A6  (via drill 0.3)
  Top 0.15: v27.58,30.96 27.86,30.96 27.86,33.4 27.89,33.43 28.27,33.43 28.3,33.45 28.3,33.98 28.32,34.01 28.42,34.01 28.42,34.72 28.4,34.75 28.25,34.75 28.22,34.77 28.22,34.8 28.19,34.82 28.19,37.9 28.22,37.92 28.93,37.92 | 28.93,37.92 29.16,37.92 29.16,41.17 29.19,41.2 29.84,41.2 J8.3 | v33.96,20.32 v33.96,22.17 | v38.25,22.4 38.25,23.85 38.23,23.88 38.12,23.88 38.12,23.98 38.1,24 38,24 38,24.03 37.97,24.05 37.49,24.05 37.49,33.27 37.52,33.3 37.72,33.3 v37.72,35.2 | v28.93,37.36 28.93,37.92
  Bottom 0.15: v27.58,30.96 27.58,30.63 27.56,30.61 24.16,30.61 24.16,30.73 24.13,30.76 22.66,30.76 22.35,30.46 21.69,30.46 21.69,29.44 CONTROL-UNIT.31 | JP6.7 v33.96,20.32 | v33.96,22.17 38.23,22.17 38.25,22.2 v38.25,22.4 | v37.72,35.2 37.72,34.98 33.91,34.98 33.88,35 33.88,37.36 32.89,37.36 32.87,37.34 32.87,37.14 28.96,37.14 28.93,37.16 v28.93,37.36
M32_A7  (via drill 0.3)
  Top 0.15: v14.71,25.25 13.23,25.25 13.23,24.71 13.21,24.69 11.71,24.69 11.71,33.48 11.74,33.5 13.82,33.5 | 13.82,33.5 13.99,33.5 v13.99,37.52 | v18.47,37.29 18.47,41.17 18.49,41.2 19.69,41.2 J9.3 | v37.19,21.34 37.19,29.44 37.16,29.46 34.29,29.46 34.29,29.79 34.27,29.82 34.16,29.82 34.16,37.97 34.19,38 34.39,38 34.39,38.94 34.37,38.96 33.33,38.96 v33.33,36.83 | v25.81,36.83 25.81,33.15 25.78,33.12 24.44,33.12 24.44,32.36 24.41,32.33 v23.47,32.33 | v14.78,32.33 13.82,32.33 13.82,33.5
  Bottom 0.15: v14.71,25.25 15.24,25.25 15.24,25.81 15.26,25.83 21.31,25.83 21.31,26.04 21.34,26.06 23.34,26.06 23.34,27.05 23.32,27.08 23.09,27.08 23.09,27.37 23.06,27.55 20.9,27.55 20.9,29.41 CONTROL-UNIT.30 | v13.99,37.52 18.44,37.52 18.47,37.49 v18.47,37.29 | JP6.8 30.73,20.32 30.76,20.34 30.76,21.34 v37.19,21.34 | v25.81,36.83 v33.33,36.83 | v23.47,32.33 18.8,32.33 18.77,32.31 18.77,32.26 17.98,32.26 17.96,32.28 17.96,32.33 v14.78,32.33
M32_B0  (via drill 0.3)
  Top 0.15: v33.86,38.43 33.86,29.59 33.88,29.57 33.98,29.57 33.98,28.8 33.96,28.78 33.76,28.78 v33.76,22.94
  Bottom 0.15: v33.86,38.43 29.77,38.43 29.77,38.23 29.74,38.2 24.66,38.2 24.66,38.28 24.64,38.3 24.56,38.3 R6.1 | v33.76,22.94 33.76,22.86 JP6.9 30.99,22.86 30.96,22.89 30.96,22.91 30.94,22.94 30.91,22.94 30.89,22.96 30.89,22.99 30.86,23.01 30.84,23.01 30.81,23.04 30.81,23.06 30.79,23.09 30.76,23.09 30.73,23.11 30.73,23.14 30.71,23.16 30.68,23.16 30.66,23.19 30.66,23.22 30.63,23.24 30.61,23.24 30.58,23.27 30.58,23.29 30.56,23.32 30.53,23.32 30.51,23.34 30.51,23.37 30.48,23.39 30.46,23.39 30.43,23.42 30.43,23.44 30.4,23.47 30.38,23.47 30.35,23.5 30.35,23.52 30.33,23.55 30.3,23.55 30.28,23.57 30.28,23.6 30.25,23.62 30.23,23.62 30.2,23.65 30.2,23.83 30.18,23.85 30,23.85 30,23.88 29.97,23.9 29.95,23.9 29.92,23.93 29.92,23.95 29.9,23.98 29.87,23.98 29.84,24 29.84,24.03 29.82,24.05 29.79,24.05 29.77,24.08 29.77,24.13 29.74,24.16 28.5,24.16 28.5,24.36 28.47,24.38 27.51,24.38 27.51,23.19 27.48,23.16 26.44,23.16 26.16,22.94 25.96,22.84 25.12,22.84 CONTROL-UNIT.40
M32_B1
  Bottom 0.15: JP6.10 26.75,22.86 26.72,22.84 26.72,22.81 26.7,22.78 26.67,22.78 26.65,22.76 26.65,22.73 26.62,22.71 26.59,22.71 26.57,22.68 26.57,22.66 26.54,22.63 26.52,22.63 26.49,22.61 26.49,22.55 26.47,22.53 26.44,22.53 26.14,22.05 26.11,22.02 25.12,22.02 CONTROL-UNIT.41
M32_B2  (via drill 0.3)
  Top 0.15: v22.94,19.53 23.24,19.53 23.27,19.56 24.03,19.56 v24.03,18.49 | v32.87,18.77 32.89,18.8 32.89,19.15 32.92,19.18 32.92,24.74 32.89,24.77 31.75,24.77 JP6.11
  Bottom 0.15: v22.94,19.53 22.94,21.21 22.96,21.23 CONTROL-UNIT.42 | v24.03,18.49 24.03,18.72 27.41,18.72 27.43,18.74 28.22,18.74 28.25,18.77 v32.87,18.77
M32_B3  (via drill 0.3)
  Top 0.15: v30.05,21.31 30.28,21.31 30.28,23.24 30.25,23.27 30.15,23.27 30.12,23.29 30.12,23.44 30.1,23.47 29.95,23.47 29.95,23.6 29.92,23.62 29.92,23.65 29.9,23.67 29.9,24.74 29.87,24.77 29.21,24.77 JP6.12
  Bottom 0.15: v30.05,21.31 28.22,21.31 28.22,20.45 28.19,20.42 25.12,20.42 CONTROL-UNIT.43
M32_B4  (via drill 0.3)
  Top 0.15: 22.5,29.34 22.53,29.34 22.53,29.39 22.55,29.41 22.61,29.41 22.63,29.44 22.63,29.46 22.66,29.49 22.68,29.49 22.71,29.52 22.71,29.54 22.73,29.57 22.76,29.57 22.78,29.59 22.78,29.62 22.81,29.64 22.84,29.64 22.86,29.67 22.86,29.74 22.89,29.77 23.5,29.77 IC3.3 23.5,31.65 23.65,31.65 23.67,31.67 23.93,32.03 25.12,32.03 26.11,33.02 26.11,36.3 26.54,36.3 26.57,36.32 26.57,40.97 v26.34,40.97 | 22.5,29.34 X2.3 | v27.76,21.62 v27.76,19.63 | v42.16,21.87 42.39,21.87 42.39,32.39 42.37,32.41 42.01,32.41 42.01,32.61 41.99,32.64 41.91,32.64 41.91,35.43 41.94,35.46 42.27,35.46 v42.27,38.56 | CAN-CONTROLLER.16 16.13,19.18 16.15,19.2 16.43,20.98 16.43,26.01 16.46,26.04 16.66,26.04 v16.66,26.8 | v22.03,26.95 22.5,27.3 22.5,29.34
  Bottom 0.15: v27.76,19.63 25.12,19.63 CONTROL-UNIT.44 | v27.76,21.62 29.59,21.62 29.62,21.64 29.62,21.84 30.73,21.84 30.76,21.82 30.76,21.64 36.73,21.64 36.96,21.87 v42.16,21.87 | v42.27,38.56 34.42,38.56 34.39,38.58 34.39,38.96 33.43,38.96 33.4,38.94 33.4,38.73 28.27,38.73 28.25,38.76 28.25,40.97 v26.34,40.97 | v16.66,26.8 16.66,27.3 19.85,27.3 20.21,26.95 v22.03,26.95
M32_B5  (via drill 0.3)
  Top 0.15: v25.45,17.37 25.45,14.45 25.48,14.43 25.68,14.43 v25.68,9.2 | v12.7,9.09 v12.7,16.99 12.7,17.15 12.72,17.17 13.59,17.17 CAN-CONTROLLER.14 | v6.45,28.52 6.45,22.48 6.48,22.45 6.63,22.45 6.63,22.43 6.65,22.4 6.68,22.4 v6.68,16.79
  Bottom 0.15: 23.29,17.65 23.29,17.8 CONTROL-UNIT.1 | v25.45,17.37 25.17,17.93 23.57,17.93 23.29,17.65 | 23.29,17.65 23.29,17.37 | v25.68,9.2 25.68,9.09 24.82,9.09 24.79,9.07 24.79,8.87 16.97,8.87 16.94,8.89 16.94,9.09 v12.7,9.09 | JP7.13 6.43,28.58 6.45,28.55 v6.45,28.52 | v6.68,16.79 7.95,16.79 7.98,16.81 7.98,16.99 v12.7,16.99
M32_B6  (via drill 0.3)
  Top 0.15: v14.86,20.9 CAN-CONTROLLER.15 | v6.99,27.41 6.76,27.41 6.76,23.42 6.78,23.39 7.52,23.39 7.52,22.43 7.49,22.4 7.29,22.4 7.29,18.44 7.31,18.41 7.9,18.41 7.9,15.06 7.92,15.04 8.64,15.04 8.64,12.52 8.66,12.5 8.71,12.5 8.74,12.47 8.74,12.45 8.76,12.42 8.76,7.49 8.79,7.47 v8.81,7.47 | v17.27,7.72 17.83,7.72 17.86,7.75 17.86,7.77 17.88,7.8 17.91,7.8 17.93,7.82 17.93,7.85 17.96,7.87 17.98,7.87 18.01,7.9 18.01,7.92 18.03,7.95 18.06,7.95 v18.06,13.95 | v19.46,14.53 v19.46,20.62
  Bottom 0.15: 19.46,20.68 17.86,20.68 17.83,20.7 17.83,20.9 v14.86,20.9 | 19.46,20.68 21.97,20.68 21.97,19.23 22,19.2 22.5,19.2 CONTROL-UNIT.2 | JP7.14 3.43,28.58 3.45,28.55 3.45,27.41 v6.99,27.41 | v8.81,7.47 15.06,7.47 15.09,7.49 15.09,7.54 15.11,7.57 15.14,7.57 15.16,7.6 15.16,7.62 15.19,7.65 15.22,7.65 15.24,7.67 15.24,7.7 15.26,7.72 v17.27,7.72 | v18.06,13.95 19.43,13.95 19.46,13.97 v19.46,14.53 | v19.46,20.62 19.46,20.68
M32_B7  (via drill 0.3)
  Top 0.15: v21.44,21.21 v21.44,19.02 | 12.32,21.67 v14.71,21.67 | 12.32,21.67 CAN-CONTROLLER.13 | JP7.15 4.45,29.59 4.47,29.57 4.85,29.57 4.85,29.52 4.88,29.49 5.23,29.49 5.23,29.26 5.26,29.23 5.41,29.23 5.44,29.21 5.44,29.08 5.46,29.06 7.52,29.06 v7.52,23.93 | v11.58,23.47 11.68,23.47 11.68,21.74 11.71,21.72 12.27,21.72 12.32,21.67
  Bottom 0.15: v21.44,19.02 21.69,19.02 21.69,17.83 CONTROL-UNIT.3 | v21.44,21.21 15.32,21.21 15.29,21.23 15.29,21.67 v14.71,21.67 | v7.52,23.93 7.52,23.47 v11.58,23.47
M32_C0  (via drill 0.3)
  Top 0.15: v12.29,25.22 12.93,25.22 v12.93,32.97 | v17.76,42.11 17.76,33.71 17.78,33.68 18.14,33.68 v18.14,33.5 | JP2.3 12.06,38.15 12.09,38.12 v13.39,38.12
  Bottom 0.15: v12.29,25.22 13.49,25.22 CONTROL-UNIT.19 | EEPROM_DATA.6 12.06,33.02 12.09,33 12.9,33 v12.93,32.97 12.95,33.05 12.95,33.6 18.06,33.6 18.09,33.58 18.09,33.55 v18.14,33.5 18.14,33.33 19.53,33.33 19.56,33.3 19.56,33.02 EEPROM_SYSTEM.6 | R4.2 16.51,42.11 v17.76,42.11 17.55,42.06 17.55,39.34 17.53,39.32 15.34,39.32 15.32,39.29 15.24,39.29 15.24,39.22 15.22,39.19 15.14,39.19 15.14,38.48 14.94,38.28 14.94,38.18 14.91,38.15 13.41,38.15 v13.39,38.12
M32_C1  (via drill 0.3)
  Top 0.15: v14.71,26.01 14.2,26.01 14.2,31.7 | 14.2,31.7 14.17,31.73 v13.72,31.73 | v15.6,43.48 15.6,38.61 15.57,38.58 15.14,38.58 15.14,38.48 14.94,38.28 14.94,36.83 14.96,36.8 15.39,36.8 15.39,36.47 15.42,36.45 15.47,36.45 15.49,36.42 15.49,36.4 15.52,36.37 15.54,36.37 15.57,36.35 15.57,36.32 15.6,36.3 15.62,36.3 15.65,36.27 15.65,36.25 15.67,36.22 15.7,36.22 15.72,36.2 15.72,31.78 15.7,31.75 14.25,31.75 14.2,31.7
  Bottom 0.15: R5.2 7.62,42.11 8.51,42.11 8.53,42.09 8.53,41.4 11.4,41.4 11.43,41.43 11.43,42.55 JP2.4 12.88,42.55 12.9,42.57 12.9,43.13 13.84,43.13 13.87,43.16 13.87,43.33 14.05,43.33 14.07,43.36 14.07,43.48 v15.6,43.48 | v14.71,26.01 13.51,26.01 CONTROL-UNIT.20 | EEPROM_DATA.5 13.69,31.75 v13.72,31.73 13.79,31.65 14.12,31.65 14.15,31.62 14.15,31.6 14.17,31.57 14.2,31.57 14.22,31.55 14.22,31.52 14.25,31.5 14.28,31.5 14.3,31.47 14.3,31.42 14.33,31.39 15.19,31.39 15.19,31.19 15.22,31.17 17.83,31.17 17.88,31.22 17.88,31.29 17.91,31.32 17.98,31.32 17.98,31.34 18.01,31.37 18.03,31.37 18.06,31.39 18.06,31.45 18.09,31.47 19.53,31.47 19.53,31.73 19.56,31.75 EEPROM_SYSTEM.5
M32_C2  (via drill 0.3)
  Top 0.15: v10.44,24.41 11.05,24.41 11.05,22.96 11.07,22.94 11.38,22.94 11.38,21.57 11.4,21.54 11.46,21.54 11.48,21.51 11.48,21.49 11.51,21.46 11.53,21.46 11.56,21.44 11.56,21.41 11.58,21.39 11.61,21.39 11.63,21.36 11.63,19.76 11.66,19.74 11.66,14.73 11.63,14.71 11.63,5.28 11.66,5.26 11.81,5.26 v11.81,0.74 | v33.45,0.74 33.45,10.67 33.43,10.69 33.22,10.69 33.22,17.22 33.2,17.25 v33,17.25
  Bottom 0.15: v10.44,24.41 10.44,24.44 10.47,24.46 11.46,24.46 11.46,24.49 11.48,24.51 11.51,24.51 11.53,24.54 11.53,24.56 11.56,24.59 11.58,24.59 11.61,24.61 11.61,24.64 11.63,24.66 11.66,24.66 11.68,24.69 11.68,26.8 11.71,26.82 13.49,26.82 CONTROL-UNIT.21 | v11.81,0.74 11.81,0.48 33.43,0.48 33.45,0.51 v33.45,0.74 | v33,17.25 33,17.48 39.27,17.48 39.5,17.25 42.67,17.25 42.7,17.27 42.7,27.94 JP6.13
M32_C3  (via drill 0.3)
  Top 0.15: v15.49,26.9 15.52,26.92 15.52,30.07 15.54,30.1 16.33,30.1 v16.33,38.05 | v19,37.82 20.68,37.82 v20.68,36.35 | v32.74,34.8 32.74,29.52 32.72,29.49 31.22,29.49 31.22,28.75 31.19,28.73 31.14,28.73 31.14,28.68 31.12,28.65 31.06,28.65 31.04,28.63 29.21,28.63 JP6.14
  Bottom 0.15: v15.49,26.9 15.49,27.58 15.47,27.61 13.51,27.61 CONTROL-UNIT.22 | v16.33,38.05 16.33,37.82 v19,37.82 | v20.68,36.35 20.68,36.14 22.45,36.14 22.48,36.12 22.48,35.2 24.05,35.2 24.08,35.18 24.08,34.87 28.35,34.87 28.37,34.85 28.37,34.62 29.84,34.62 29.87,34.65 29.87,34.75 30.58,34.75 30.61,34.72 30.61,34.57 32.72,34.57 32.74,34.59 v32.74,34.8
M32_C4  (via drill 0.3)
  Top 0.15: v15.8,30.63 16.03,30.63 16.03,36.32 15.7,36.65 15.7,38.02 15.67,38.05 v15.47,38.05 | v22.96,39.78 24.46,39.78 v24.46,36.88 | v30.73,36.3 30.73,32.74 30.71,32.72 30.38,32.72 30.38,29.79 30.35,29.77 v30.15,29.77
  Bottom 0.15: v15.8,30.63 15.32,30.63 15.32,29.44 CONTROL-UNIT.23 | v15.47,38.05 15.47,39.01 19.13,39.01 19.15,39.04 19.15,39.55 22.94,39.55 22.96,39.57 v22.96,39.78 | v24.46,36.88 24.46,36.3 26.31,36.3 26.34,36.32 26.34,36.53 30.71,36.53 30.73,36.5 v30.73,36.3 | v30.15,29.77 31.01,29.77 31.04,29.79 31.04,30.48 JP6.15
M32_C5  (via drill 0.3)
  Top 0.15: v9.14,29.64 9.12,29.62 9.12,15.06 9.09,15.04 8.94,15.04 8.94,12.7 8.97,12.67 9.07,12.67 9.07,8.89 9.09,8.87 v9.3,8.87 | v21.95,8.03 21.97,8.05 v21.97,9.58 | v33.76,11.13 33.53,11.13 33.53,19.15 33.5,19.18 33.22,19.18 33.22,24.74 33.25,24.77 33.45,24.77 v33.45,29.23
  Bottom 0.15: v9.14,29.64 9.14,28.5 9.17,28.47 14.66,28.47 14.66,28.4 14.68,28.37 16.1,28.37 16.1,29.41 CONTROL-UNIT.24 | v9.3,8.87 9.3,7.77 14.88,7.77 15.14,8.03 16.81,8.03 16.84,8.05 16.84,8.13 16.92,8.13 16.94,8.15 16.94,8.23 16.97,8.26 21.92,8.26 21.95,8.23 v21.95,8.03 | v21.97,9.58 21.97,11.05 22.55,11.05 22.58,11.07 22.58,11.2 27.66,11.2 27.69,11.23 31.78,11.23 31.8,11.2 31.8,10.9 33.73,10.9 33.76,10.92 v33.76,11.13 | v33.45,29.23 29.64,29.23 29.62,29.26 29.62,30.48 JP6.16
M32_C6  (via drill 0.3)
  Top 0.15: v16.87,30.63 16.64,30.63 16.64,37.39 16.66,37.41 17.45,37.41 17.45,41.66 17.42,41.68 17.22,41.68 17.22,43.94 17.25,43.97 27.41,43.97 27.41,41.48 27.38,41.45 27.18,41.45 27.18,37.92 27.2,37.9 27.89,37.9 v27.89,34.34
  Bottom 0.15: v16.87,30.63 16.92,30.63 16.92,29.44 CONTROL-UNIT.25 | v27.89,34.34 27.91,34.32 29.59,34.32 29.62,34.29 29.62,33.96 29.64,33.93 29.72,33.93 29.74,33.91 29.74,33.83 29.82,33.83 29.84,33.81 29.84,33.73 29.92,33.73 29.95,33.71 29.95,33.68 31.01,33.68 31.04,33.66 31.04,33.02 JP6.17
M32_C7
  Bottom 0.15: JP6.18 28.5,33.02 28.5,32.46 28.47,32.44 24,32.44 24,31.5 23.98,31.47 22.07,31.47 22.07,31.19 22.05,31.17 18.26,31.17 17.96,30.86 17.7,30.86 17.7,29.44 CONTROL-UNIT.26
M32_D0  (via drill 0.3)
  Top 0.15: v26.04,29.46 IC3.1 | v24.03,29.46 23.09,29.46 23.06,29.44 23.06,29.41 23.04,29.39 23.01,29.39 22.99,29.36 22.99,29.34 22.96,29.31 22.94,29.31 22.91,29.29 22.91,29.26 22.89,29.23 22.86,29.23 22.84,29.21 22.84,29.19 22.81,29.16 v22.81,26.59 | v16.03,26.37 16.03,25.55 16,25.53 15.9,25.53 15.9,24.74 15.88,24.71 14.61,24.71 14.58,24.69 14.58,24.66 14.55,24.64 14.53,24.64 14.5,24.61 14.5,24.59 14.48,24.56 14.45,24.56 14.43,24.54 14.43,24.51 14.4,24.49 14.38,24.49 14.35,24.46 14.35,24.41 14.33,24.38 12.22,24.38 v12.22,23.04 | v6.99,22.86 6.99,17.91 7.01,17.88 v7.21,17.88 | JP2.1 9.53,38.05 9.5,38.02 8.1,38.02 8.1,33 8.13,32.97 v8.2,32.97 | v9.78,30.99 v9.78,32.97 | v10.85,30.99 10.62,30.99 10.62,29.52 10.49,29.39 10.49,29.36 10.47,29.36 10.44,29.34 10.44,29.31 10.41,29.29 10.39,29.29 10.39,24.97 10.36,24.94 9.91,24.94 v9.91,22.86
  Bottom 0.15: JP7.5 7.21,18.41 | 7.21,18.41 14.43,18.41 14.43,19.05 14.45,19.08 14.53,19.08 14.55,19.1 14.55,19.15 14.58,19.18 16.31,19.18 16.33,19.15 16.33,19.1 16.36,19.08 16.92,19.08 16.92,17.83 CONTROL-UNIT.9 | v24.03,29.46 v26.04,29.46 | v22.81,26.59 22.81,26.37 21.03,26.37 21.01,26.34 21.01,26.14 16.05,26.14 16.03,26.16 v16.03,26.37 | v12.22,23.04 12.22,22.71 12.19,22.71 12.17,22.68 12.17,22.63 9.91,22.63 | 9.91,22.63 7.01,22.63 6.99,22.66 v6.99,22.86 | 7.21,18.41 v7.21,17.88 | v9.78,32.97 v8.2,32.97 | v10.85,30.99 v9.78,30.99 | 9.91,22.63 v9.91,22.86
M32_D1  (via drill 0.3)
  Top 0.15: IC3.4 22.23,30.15 22.2,30.12 18.74,30.12 18.74,29.59 18.72,29.57 18.01,29.57 | 18.01,29.57 18.01,27 17.98,26.98 17.7,26.98 17.7,22.91 17.73,22.89 17.93,22.89 17.93,21.95 17.91,21.92 16.74,21.92 v16.74,16.61 | JP2.2 9.53,41.83 9.55,41.81 10.52,41.81 v10.52,36.88 | v17.22,36.88 17.45,36.88 17.45,33.53 17.48,33.5 17.53,33.5 17.55,33.48 17.55,33.45 17.58,33.43 17.6,33.43 17.6,29.64 17.63,29.62 17.96,29.62 18.01,29.57
  Bottom 0.15: JP7.6 2.62,18.41 2.62,17.37 2.64,17.35 7.75,17.35 7.75,18.09 7.77,18.11 14.73,18.11 14.73,18.85 14.76,18.87 16.1,18.87 CONTROL-UNIT.10 16.1,17.76 16.1,16.81 16.13,16.79 16.74,16.79 v16.74,16.61 | v17.22,36.88 v10.52,36.88
M32_D2  (via drill 0.3)
  Top 0.15: v6.02,16.26 5.79,16.26 5.79,19.69 5.77,19.71 4.45,19.71 JP7.7
  Bottom 0.15: v6.02,16.26 7.11,16.26 7.11,16.46 7.14,16.48 8.26,16.48 8.26,16.66 8.28,16.69 12.24,16.69 12.24,16.48 12.27,16.46 15.32,16.46 15.32,17.8 CONTROL-UNIT.11
M32_D3
  Bottom 0.15: JP7.8 2.62,20.96 2.62,19.91 2.64,19.89 5.99,19.89 5.99,20.09 6.02,20.12 12.47,20.12 12.47,19.66 12.5,19.63 13.49,19.63 CONTROL-UNIT.12
M32_D4  (via drill 0.3)
  Top 0.15: v5.56,20.42 5.44,20.42 5.44,22.76 5.41,22.78 4.45,22.78 JP7.9
  Bottom 0.15: v5.56,20.42 13.49,20.42 CONTROL-UNIT.13
M32_D5
  Bottom 0.15: JP7.10 2.59,23.5 2.59,22.25 2.62,22.23 2.69,22.23 2.72,22.2 2.72,22.15 2.74,22.12 5.44,22.12 5.44,21.51 5.46,21.49 6.58,21.49 6.58,21.69 6.6,21.72 12.47,21.72 12.47,21.26 12.5,21.23 13.49,21.23 CONTROL-UNIT.14
M32_D6  (via drill 0.3)
  Top 0.15: v6.15,22.02 6.15,25.38 6.12,25.4 4.45,25.4 JP7.11
  Bottom 0.15: v6.15,22.02 13.49,22.02 CONTROL-UNIT.15
M32_D7
  Bottom 0.15: JP7.12 2.9,26.04 2.9,22.45 2.92,22.43 5.44,22.43 5.44,22.53 5.46,22.55 6.4,22.55 6.4,22.53 6.43,22.5 6.58,22.5 6.58,22.35 6.6,22.33 12.47,22.33 12.47,22.53 12.5,22.55 12.55,22.58 12.75,22.81 12.78,22.84 13.49,22.84 CONTROL-UNIT.16
M32_RESET  (via drill 0.3)
  Top 0.15: v17.4,20.37 CAN-CONTROLLER.17 | v27.05,16.71 26.8,14.48 26.62,14.45 26.59,14.43 26.29,14.43 26.29,10.06 26.31,10.03 v26.75,10.03 | v30.48,10.03 30.48,8.36 30.46,8.33 30.25,8.33 30.25,1.29 30.28,1.27 v30.48,1.27 | v12.34,1.27 12.12,1.27 12.12,5.64 12.14,5.66 v12.17,5.66 | v1.32,5.72 1.32,12.4 1.29,12.42 1.19,12.42 1.19,12.57 1.17,12.6 0.89,12.6 0.89,30.46 0.91,30.48 1.91,30.48 JP7.16
  Bottom 0.15: v17.4,20.37 18.82,20.37 18.82,19.05 18.85,19.02 20.9,19.02 CONTROL-UNIT.4 20.9,17.76 20.9,16.71 21.06,16.71 21.08,16.69 22.55,16.69 22.81,16.43 25.25,16.43 25.5,16.69 27.03,16.69 v27.05,16.71 | JP7.16 2.62,31.12 2.62,30.15 2.64,30.12 5.44,30.12 5.44,31.29 5.46,31.32 6.99,31.32 R1.1 6.43,31.37 6.43,34.7 6.45,34.72 6.99,34.72 C6.1 | v30.48,10.03 v26.75,10.03 | v30.48,1.27 29.72,1.27 29.41,0.96 29.41,0.79 12.37,0.79 12.34,0.81 v12.34,1.27 | v12.17,5.66 12.17,5.82 8.64,5.82 8.61,5.84 8.61,5.94 7.9,5.94 7.87,5.92 7.87,5.77 4.65,5.77 4.62,5.79 4.62,5.89 4.52,5.89 4.5,5.92 4.5,5.94 4.01,5.94 3.96,5.89 1.35,5.89 1.32,5.87 v1.32,5.72
M32_XTAL1  (via drill 0.3)
  Top 0.15: v15.49,19.84 15.47,19.81 15.47,16.36 15.44,16.33 13.97,16.33 PAD4.1
  Bottom 0.15: v15.49,19.84 15.49,19.51 15.52,19.48 16.51,19.48 16.51,19.41 16.54,19.38 17.7,19.38 CONTROL-UNIT.8
M32_XTAL2  (via drill 0.3)
  Top 0.15: v18.03,19.84 18.01,19.81 18.01,15.98 17.98,15.95 17.78,15.95 PAD6.1
  Bottom 0.15: v18.03,19.84 18.52,19.84 18.52,17.83 CONTROL-UNIT.7
N$1  (via drill 0.3)
  Top 0.15: v27.71,40.44 27.71,39.37 LED1.A
  Bottom 0.15: v27.71,40.44 27.71,40.11 26.26,40.11 26.24,40.08 26.24,39.37 R6.2
N$2  (via drill 0.3 pad 0.6)
  Top 0.15: X2.2 21.86,28.07 v21.9,28.11 | v24.64,28.83 24.77,29.21 IC3.2
  Bottom 0.15: v21.9,28.11 23.41,28.11 23.75,28.45 v24.64,28.83
N$4  (via drill 0.3)
  Top 0.15: v26.19,7.04 26.21,7.06 26.21,9.63 26.19,9.65 25.98,9.65 25.98,15.09 26.01,15.11 26.04,15.11 CAN-DRIVER.8
  Bottom 0.15: v26.19,7.04 26.19,6.73 26.16,6.71 20.52,6.71 20.52,6.99 R2.1
N$5
  Top 0.15: C7.1 6.99,35.76 7.67,35.76 7.67,37.9 7.65,37.92 7.49,37.92 7.49,43.26 7.52,43.28 8.53,43.28 8.53,43.94 8.56,43.97 10.82,43.97 10.82,37.59 10.85,37.57 11.05,37.31 Q1.1 10.34,34.93 10.31,34.9 10.31,29.64 10.29,29.64 10.26,29.62 10.26,29.59 10.24,29.57 10.21,29.57 10.19,29.54 10.19,29.52 10.16,29.49 10.11,29.49 10.08,29.46 9.83,29.01 9.8,29.01 9.78,28.98 CAN-CONTROLLER.8
N$6
  Bottom 0.15: JP_TERM.2 26.21,10.16 26.21,8.05 26.24,8.03 29.41,8.03 29.41,6.99 R3.2
N$7  (via drill 0.3)
  Top 0.15: 23.88,37.9 23.88,38.15 23.85,38.18 21.44,38.18 21.44,34.95 21.41,34.93 Q1.2 | 23.88,37.9 23.88,36.3 23.9,36.27 23.93,36.27 23.95,36.25 23.95,36.22 23.98,36.2 24.05,36.2 24.08,36.17 24.08,35.76 24.77,35.76 C8.1 | CAN-CONTROLLER.7 11.05,25.07 11.02,25.04 v10.92,25.04 | v3.61,25.04 3.38,25.04 3.38,23.11 3.4,23.09 3.51,23.09 3.53,23.06 3.53,22.96 3.56,22.94 3.61,22.94 3.61,21.97 3.58,21.95 3.45,21.95 3.45,19.43 3.48,19.41 5.49,19.41 v5.49,14.88 | v12.17,14.48 12.17,12.01 12.14,11.99 11.94,11.99 11.94,6.22 11.96,6.2 12.93,6.2 v12.93,5.94 | v26.62,6.4 27.94,6.4 v27.94,10.59 | v40.26,10.59 40.26,18.21 40.23,18.24 40.03,18.24 40.03,29.01 40.06,29.03 40.26,29.03 v40.26,34.27 | v30.2,34.21 v30.2,37.9 | v23.93,37.9 23.88,37.9
  Bottom 0.15: v3.61,25.04 v10.92,25.04 | v5.49,14.88 5.49,14.63 5.59,14.63 5.61,14.61 5.61,14.55 5.64,14.53 5.72,14.53 5.74,14.5 5.74,14.28 5.77,14.25 12.14,14.25 12.17,14.28 v12.17,14.48 | v12.93,5.94 22.38,5.94 22.4,5.97 22.4,6.4 v26.62,6.4 | v27.94,10.59 v40.26,10.59 | v40.26,34.27 30.23,34.27 30.2,34.24 v30.2,34.21 | v30.2,37.9 v23.93,37.9
RXCAN  (via drill 0.3)
  Top 0.15: v17.4,22.45 CAN-CONTROLLER.2 | v22.05,22.58 22.2,22.58 22.2,21.74 22.23,21.72 CAN-DRIVER.4
  Bottom 0.15: v17.4,22.45 22.02,22.45 22.05,22.48 v22.05,22.58
TXCAN  (via drill 0.3)
  Top 0.15: CAN-CONTROLLER.1 18.67,25.32 18.69,25.3 v18.82,25.3 | v20.17,25.3 20.4,25.3 20.4,22.55 20.42,22.53 20.52,22.53 20.52,14.02 20.5,13.99 19.15,13.99 19.15,13.46 19.13,13.44 19.08,13.44 19.05,13.41 19.05,13.39 19.02,13.36 19,13.36 18.97,13.33 18.97,13.31 18.95,13.28 18.92,13.28 18.9,13.26 18.9,13.23 18.87,13.21 18.85,13.21 18.82,13.18 18.82,13.16 18.8,13.13 18.77,13.13 18.77,7.8 18.8,7.77 20.02,7.77 v20.02,1.73 | v28.47,8.56 28.47,11.68 28.45,11.71 28.22,11.71 v28.22,14.4 | v24.13,14.4 24.16,14.43 24.16,17.17 24.18,17.2 24.46,17.2 24.46,18.16 24.56,18.26 24.56,18.29 24.59,18.31 24.61,18.31 24.64,18.34 24.64,18.36 24.66,18.39 24.69,18.39 24.71,18.41 24.71,18.44 24.74,18.47 24.77,18.47 24.79,18.49 24.79,18.52 24.82,18.54 24.84,18.54 24.87,18.57 24.87,18.59 24.89,18.62 24.92,18.62 24.94,18.64 24.94,18.72 24.97,18.74 26.04,18.74 CAN-DRIVER.1
  Bottom 0.15: v20.17,25.3 v18.82,25.3 | v20.02,1.73 20.02,1.5 27.51,1.5 27.53,1.52 27.53,5.23 27.64,5.23 28.04,5.64 28.04,5.94 30.35,5.94 30.38,5.97 30.38,8.26 29.62,8.26 29.59,8.28 29.59,8.33 28.5,8.33 28.47,8.36 v28.47,8.56 | v28.22,14.4 v24.13,14.4
VCC  (via drill 0.3)
  Top 0.25: v31.75,40.03 JP6.19 | C4.1 6.99,30.66 6.27,30.66 6.25,30.63 6.25,29.64 v5.77,29.64 5.66,29.69 5.54,29.69 5.54,35.46 | 5.54,35.46 5.51,35.48 4.45,35.48 JP7.19 | 14.35,36.35 14.35,37.03 14.38,37.06 14.58,37.06 14.58,39.27 14.61,39.29 JP2.5 | v14.35,33.02 14.35,36.35 | v6.53,39.45 6.53,39.09 5.92,39.09 5.89,39.07 5.89,35.51 5.64,35.51 5.54,35.46 | 14.35,36.35 v14.53,36.35 | CAN-DRIVER.3 23.5,21.72 23.44,21.72 23.42,22.5 C3.1 23.16,23.6 23.16,23.7 22.89,23.72 v22.05,24.23 | IC3.8 26.04,24.26 26.06,24.23 v26.31,24.23 | v8.89,6.6 10.16,6.6 C11.+ | v19.46,28.22 19.43,28.19 19.43,23.62 | 19.43,21.23 19.43,23.62 | 19.43,21.23 19.41,21.21 18.67,21.21 CAN-CONTROLLER.18 18.67,17.83 19.08,15.8 19.1,15.77 19.1,15.01 18.95,15.01 18.92,14.99 18.92,14.83 18.87,14.78 18.85,14.78 18.82,14.76 18.82,14.17 18.8,14.15 18.8,13.67 18.77,13.64 18.74,13.64 18.72,13.61 18.72,13.59 18.69,13.56 18.67,13.56 18.64,13.54 18.64,13.51 18.62,13.49 18.44,13.49 18.41,13.46 18.41,7.11 v17.73,7.11 | v19.99,16.61 20.17,16.61 20.17,21.18 20.14,21.21 19.53,21.21 19.43,21.23 | 19.43,23.62 v19.33,23.62 | v18.49,30.63 v18.49,32.79 | J9.1 24.77,43.59 24.74,43.61 21.18,43.61 21.18,39.04 21.21,39.01 v22.91,39.01
  Top 0.4: J2.1 J3.1 J4.1 J5.1 J6.1 J7.1
  Bottom 0.25: J9.1 25.48,41.91 25.5,41.94 25.5,43.92 34.27,43.92 34.29,43.89 34.29,41.91 J8.1 34.24,41.81 34.24,40.03 v31.75,40.03 | JP6.19 33.5,35.56 33.53,35.54 33.53,34.62 39.78,34.62 39.8,34.65 39.8,36.83 J7.1 | 20.09,36.3 20.09,35.56 EEPROM_SYSTEM.8 | 20.09,36.3 20.09,36.6 20.12,36.63 20.12,38.1 C1.1 20.12,38.2 20.12,39.17 20.14,39.19 22.91,39.19 v22.91,39.01 | 14.53,36.53 16.74,36.53 16.76,36.5 16.76,36.3 20.09,36.3 | 14.53,36.53 12.09,36.53 12.09,35.59 12.06,35.56 EEPROM_DATA.8 | v5.77,29.64 R1.2 | 13.89,40.01 13.89,38.99 13.87,38.96 12.27,38.96 12.27,38.1 C2.1 | JP2.5 13.89,40.01 | 13.84,40.44 13.84,40.11 13.89,40.01 | 13.84,40.44 13.84,41.02 13.82,41.05 8.48,41.05 8.48,40.46 8.46,40.44 7.62,40.44 R5.1 7.52,40.44 6.91,40.44 6.91,40.13 6.88,40.11 6.53,40.11 v6.53,39.45 | R4.1 16.51,40.44 13.84,40.44 | v14.35,33.02 EEPROM_DATA.3 17.78,33.02 17.8,33 17.8,32.79 v18.49,32.79 | v14.53,36.35 14.53,36.53 | 22.05,24.41 25.09,24.41 CONTROL-UNIT.38 25.22,24.41 26.31,24.41 v26.31,24.23 | 22.05,24.41 20.88,24.41 20.88,23.65 20.85,23.62 v19.33,23.62 CONTROL-UNIT.17 | 22.05,24.41 v22.05,24.23 | 20.09,16.61 20.09,16.36 20.9,16.36 20.93,16.33 21.9,16.33 22.43,16.05 22.43,15.24 C5.1 | 20.09,16.61 20.09,17.8 CONTROL-UNIT.5 | v8.89,6.6 11.13,6.6 IC1.2 11.28,6.6 11.84,6.6 11.86,6.63 11.86,7.11 v17.73,7.11 | v19.46,28.22 18.52,28.22 18.52,29.41 CONTROL-UNIT.27 18.52,29.54 18.52,30.12 18.49,30.15 v18.49,30.63 | v19.99,16.61 20.09,16.61
VCCSUPPLY  (via drill 0.3)
  Top 0.25: 5.92,11.15 5.92,8.89 C12.1 | 5.92,11.15 5.94,11.18 v7.42,11.18 7.52,11.13 7.52,8.46 7.8,8.46 7.82,8.43 7.82,5.79 7.72,5.79 7.7,5.77 7.7,3.4 10.13,3.4 10.16,3.38 J10.1 | v2.92,33.02 3.1,33.02 3.1,27.36 3.07,27.33 2.87,27.33 2.87,26.59 2.9,26.57 2.92,26.57 2.95,26.54 2.95,25.07 2.97,25.04 3.02,25.04 3.02,21.97 3.05,21.95 3.1,21.95 3.1,19.2 3.12,19.18 3.2,19.18 3.23,19.15 3.23,11.23 3.25,11.2 5.82,11.2 5.92,11.15
  Bottom 0.25: J10.1 14.05,1.91 14.07,1.88 14.07,1.7 17.53,1.7 17.55,1.73 17.55,3.81 X1.5 | v7.42,11.18 11.13,11.18 IC1.1 | JP7.17 2.97,33.66 2.95,33.63 2.95,33.02 v2.92,33.02

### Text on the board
Bottom: .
